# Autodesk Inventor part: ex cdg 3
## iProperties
Author: jost thierry
Created: 2004-05
Part Number: ex cdg 3
Material: Silicium
Document SubType Name: Modélisation
Designer: jost thierry
Control State: 0
Master: False
Checked Out: False
PropertySet Name: Design Tracking Control
Shininess: 20.0
Angle Display Precision: 2
Document Length Units: 11269
Document Angle Units: 11283
Document Time Units: 11279
Document Mass Units: 11290
Document Length Units Precision: 3
Document Angle Units Precision: 2
Compacted: False
PropertySet Name: _Private Model Information
Density: 1.25
Volumn: 44.000000000000036
Area: 138.00000000000006
PropertySet Name: Model Information
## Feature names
1. Extrusion1
